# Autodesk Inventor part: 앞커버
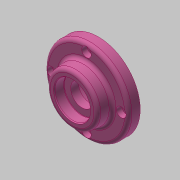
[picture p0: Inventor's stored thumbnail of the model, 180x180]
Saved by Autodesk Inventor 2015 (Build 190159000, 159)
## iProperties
Created: 2017-08
Part Number: 앞커버
Material: 알루미늄 6061
Document SubType Name: Modeling
Designer: mduedu
Density: 2.71 g/cm^3
Appearance: 분홍색
Mass: 117.251 g
Surface Area: 148.117 cm^2
Volume: 43.2662 cm^3
Author: mduedu
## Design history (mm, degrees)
sketch "스케치1"
  geometry: C1 r 35 at (0, 0); 1 further point
  constraints: 1 centre point, 1 coincident
  dimensions: "d0" = 70 diameter of C1
extrude "돌출1" new body sketch "스케치1" distance "d1" = 10; taper "d2" = 0 deg
sketch "스케치2"
  geometry: C1 r 22 at (0, 0); 1 further point
  constraints: 1 centre point, 1 coincident
  dimensions: "d3" = 44 diameter of C1
node "작업 평면1"
sketch "스케치3"
  geometry: C1 r 21 at (0, 0); 1 further point
  constraints: 1 centre point, 1 coincident
  dimensions: "d5" = 42 diameter of C1
feature "로프트1" sketch "스케치3" dims "d6" = 0, "d7" = 90 deg, "d8" = 0, "d9" = 90 deg
sketch "스케치4"
  geometry: C1 r 24 at (0, 0); 1 further point
  constraints: 1 centre point, 1 coincident
  dimensions: "d86" = 48 diameter of C1
extrude "돌출2" join sketch "스케치4" distance "d10" = 8; taper "d11" = 0 deg
hole "구멍1" diameter "d14" = 40; stored, may be unused: countersink angle "d18" = 90 deg, drill point angle "d20" = 0 deg; dims "d15" = 6, "d16" = 4, "d17" = 2, "d19" = 12, "d87" = 10, "d88" = 10
hole "구멍2" diameter "d23" = 34; stored, may be unused: countersink angle "d27" = 90 deg, drill point angle "d29" = 0 deg; dims "d21" = 10, "d22" = 10, "d24" = 6, "d25" = 4, "d26" = 2, "d28" = 3
hole "구멍3" diameter "d32" = 19; stored, may be unused: countersink angle "d36" = 90 deg, drill point angle "d38" = 0 deg; dims "d30" = 10, "d31" = 10, "d33" = 6, "d34" = 4, "d35" = 2, "d37" = 3
chamfer "모따기1" distance "d39" = 1; stored, may be unused: second distance "d40" = 2, angle "d41" = 45 deg
sketch "스케치5"
  geometry: C1 r 15 at (0, 0); 1 further point
  constraints: 1 centre point, 1 coincident
  dimensions: "d42" = 30 diameter of C1
extrude "돌출3" cut sketch "스케치5" distance "d43" = 8.3; taper "d44" = 0 deg
chamfer "모따기2" distance "d47" = 0.8; stored, may be unused: second distance "d48" = 2, angle "d49" = 30 deg
fillet "모깎기1" dims "d50" = 0.3
fillet "모깎기2" dims "d51" = 0.3
fillet "모깎기3" dims "d52" = 3
sketch "스케치6" dims "d53" = 58
  geometry: 6 further points
  constraints: 2 vertical alignment, 1 coincident, 7 other
  dimensions: "d56" = 360 deg dimension on point (0, 0) point (0, 29) (derived)
sketch "스케치9" dims "d85" = 58 (derived)
  geometry: 6 further points
  constraints: 1 coincident, 1 vertical alignment, 6 other
hole "구멍6" sketch "스케치9" at (-29, 0), (0, -29), (29, 0), (0, 29) diameter "d72" = 4.5; stored, may be unused: countersink angle "d76" = 90 deg, drill point angle "d78" = 0 deg; dims "d73" = 6, "d74" = 8, "d75" = 4.6, "d77" = 8
fillet "모깎기4" dims "d79" = 3
fillet "모깎기5" dims "d80" = 3
fillet "모깎기6" dims "d81" = 3
node "솔리드1"
other parameters: "d4" = 12
